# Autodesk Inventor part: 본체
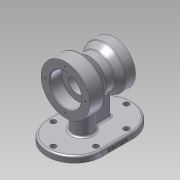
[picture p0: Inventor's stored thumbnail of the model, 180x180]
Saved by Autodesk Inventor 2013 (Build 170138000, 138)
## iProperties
Created: 2020-01
Part Number: 본체
Material: 알루미늄 6061
Document SubType Name: Modeling
Designer: Administrator
Density: 2.71 g/cm^3
Mass: 934.751 g
Surface Area: 655.218 cm^2
Volume: 344.927 cm^3
Author: Administrator
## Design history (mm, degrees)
sketch "스케치1"
  geometry: L1 (-40, 0)-(40, 0); L2 (-40, 0)-(-40, 40); L3 (-40, 40)-(-16, 40); L4 (-16, 40)-(-1.103, 27.5); L5 (-1.103, 27.5)-(13.289, 27.5); L6 (24, 35)-(40, 35); L7 (40, 35)-(40, 0); L8 (24, 35)-(13.289, 27.5); 2 further points
  constraints: 16 end point, 3 parallel, 2 perpendicular, 1 coincident, 1 horizontal, 1 midpoint
  dimensions: "d0" = 80 distance of L1.start L1.end; "d2" = 24 distance of L2.end L3.end; "d6" = 55 diameter of L5 L1; "d7" = 70 diameter of L6 L1; "d8" = 80 diameter of L3 L1; "d9" = 16 distance of L6.start L6.end; "d10" = 35 deg angle of L5 L8; "d11" = 40 deg angle of L5 L4
revolve "회전1" sketch "스케치1" stored, may be unused: angle "d12" = 90 deg
hole "구멍1" diameter "d15" = 32; stored, may be unused: countersink angle "d19" = 90 deg, drill point angle "d21" = 118 deg; dims "d13" = 10, "d14" = 10, "d16" = 6, "d17" = 52, "d18" = 20, "d20" = 8
hole "구멍2" diameter "d24" = 40; stored, may be unused: countersink angle "d28" = 90 deg, drill point angle "d30" = 0 deg; dims "d22" = 10, "d23" = 10, "d25" = 6, "d26" = 52, "d27" = 20, "d29" = 17
fillet "모깎기1" dims "d31" = 0.3
sketch "스케치2"
  geometry: L1 (-70, -70)-(70, -70); L2 (70, -70)-(70, -80); L3 (70, -80)-(-70, -80); L4 (-70, -80)-(-70, -70); 2 further points
  constraints: 8 end point, 2 parallel, 1 horizontal, 1 midpoint, 1 perpendicular, 1 vertical alignment
  dimensions: "d33" = 80 distance from line of L3 point (0, 0); "d34" = 10 distance between parallel lines of L3 L1; "d35" = 140 distance between parallel lines of L4 L2
extrude "돌출1" join sketch "스케치2" stored distance "d36" = 90; taper "d37" = 0 deg
fillet "모깎기2" dims "d38" = 45
sketch "스케치3"
  geometry: L1 (0, 0)-(50, 0) reference; L2 (50, -90)-(0, -90) reference; L3 (28.199, -40)-(55, -40); L4 (55, -40)-(55, -50); L5 (55, -50)-(28.199, -50); L6 (65, -80)-(65, -10) reference; L7 (-15, -85)-(-15, -5) reference; A1 r 45 centre (50, -45) between (50, -90) and (50, 0) reference; A2 r 45 centre (0, -45) between (0, 0) and (0, -90) reference; A3 r 16 centre (13, -45) between (28.199, -40) and (28.199, -50); A4 r 45 centre (0, -45) between (0, 0) and (0, -90); 2 further points
  constraints: 8 end point, 5 point on circle, 2 centre point, 2 parallel, 1 coincident, 1 horizontal alignment, 1 perpendicular
  dimensions: "d41" = 32 diameter of A3; "d42" = 5 distance from line of A1.centre L3; "d43" = 10 distance between parallel lines of L5 L3; "d45" = 58 distance of A3.centre point (-45, -45); "d88" = 10 distance between parallel lines of L6 L4
extrude "돌출2" join sketch "스케치3" stored distance "d46" = 90; taper "d47" = 0 deg
sketch "스케치4"
  geometry: L1 (0, 0)-(50, 0) reference; L2 (50, -90)-(0, -90) reference; L3 (50, -80)-(0, -80); L4 (0, -10)-(50, -10); A1 r 45 centre (50, -45) between (50, -90) and (50, 0) reference; A2 r 45 centre (0, -45) between (0, 0) and (0, -90) reference; A3 r 35 centre (50, -45) between (50, -80) and (50, -10); A4 r 35 centre (0, -45) between (0, -10) and (0, -80); A5 r 45 centre (50, -45) between (50, -90) and (50, 0) reference; 8 further points
  constraints: 6 point on circle, 5 coincident, 4 end point, 2 centre point, 3 other
  dimensions: "d48" = 10 distance between parallel lines of L1 L4
hole "구멍3" sketch "스케치4" at (-35, -45), (85, -45), (50, -10), (50, -80), (0, -80), (0, -10) diameter "d49" = 9; stored, may be unused: countersink angle "d53" = 90 deg, drill point angle "d55" = 0 deg; dims "d50" = 6, "d51" = 52, "d52" = 20, "d54" = 17
sketch "스케치5" dims "d56" = 66
  geometry: C1 r 26 at (0, 0) reference; C2 r 40 at (0, 0) reference; 2 further points
  constraints: 2 vertical alignment, 1 coincident, 2 other
hole "구멍4" sketch "스케치5" at (0, 33) diameter "d58" = 3.242; stored, may be unused: countersink angle "d62" = 90 deg, drill point angle "d64" = 118 deg; dims "d59" = 9, "d60" = 52, "d61" = 20, "d63" = 11
sketch "스케치6" dims "d68" = 55
  geometry: C1 r 20 at (0, 0) reference; C2 r 35 at (0, 0) reference; 2 further points
  constraints: 2 vertical alignment, 1 coincident, 2 other
hole "구멍5" sketch "스케치6" at (0, 27.5) diameter "d70" = 3.242; stored, may be unused: countersink angle "d74" = 90 deg, drill point angle "d76" = 118 deg; dims "d71" = 9, "d72" = 52, "d73" = 20, "d75" = 11
fillet "모깎기3" dims "d80" = 3
chamfer "모따기1" distance "d81" = 1; stored, may be unused: second distance "d82" = 2, angle "d83" = 45 deg
fillet "모깎기5" dims "d85" = 3
fillet "모깎기6" dims "d86" = 3
fillet "모깎기7" dims "d87" = 3
fillet "모깎기8" dims "d89" = 3
sketch "스케치7"
  geometry: L1 (-25, -80)-(25, -80) reference; L2 (-70, -73)-(-70, -80) reference; 2 further points
  constraints: 1 other
  dimensions: "d90" = 4 distance from line of L1 point (0, -76); "d91" = 70 distance from line of point (0, -76) L2
feature "엠보싱1" sketch "스케치7" dims "d0" = 80, "d2" = 24, "d6" = 55, "d7" = 70, "d8" = 80, "d9" = 16, "d10" = 35 deg, "d11" = 40 deg, "d31" = 0.3, "d92" = 0.5, "d93" = 0
node "솔리드1"
pattern_circular "원형 패턴1" dims angle "d66" = 360 deg
pattern_circular "원형 패턴2" dims angle "d78" = 360 deg
